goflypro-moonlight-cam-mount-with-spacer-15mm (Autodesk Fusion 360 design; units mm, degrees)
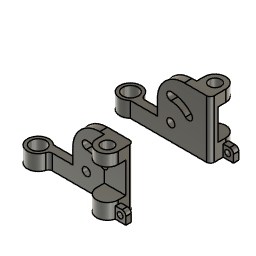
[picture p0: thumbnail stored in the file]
sketch "Skizze1" plane through (0, 0, 0) normal (0, 0, 1) x axis (1, 0, 0)
  line L1 (7.2, 0) -> (-7.2, 0)
  line L2 (7.2, 0) -> (7.2, -2)
  line L3 (-1, 0) -> (-1, 2)
  line L4 (12.8, 2) -> (-8.605, 2)
  line L5 (12.8, 2) -> (12.8, -2)
  line L6 (12.8, 0) -> (7.2, 0)
  line L7 (11, -2) -> (11, 2)
  line L8 (12.8, -2) -> (11, -2)
  circle C1 centre (-10, 0) radius 2
  circle C2 centre (10, -2) radius 1.55
  circle C3 centre (-10, 0) radius 2.8
  circle C4 centre (10, -2) radius 2.8
  point P6 (-7.2, 0)
  point P7 (7.2, -2)
  point P10 (-1, 0)
  point P12 (12.8, -2)
  point P14 (12.8, 0)
  point P15 (11, 2)
  concentric C1 C3
  concentric C2 C4
  coincident C3 P6
  horizontal L1
  coincident C4 P7
  tangent C4 L2
  perpendicular L1 L2
  perpendicular L1 L3
  coincident L1 P10
  coincident C4 P12
  tangent C4 L5
  perpendicular L4 L5
  midpoint L5 P14
  coincident L4 P15
  perpendicular L6 L7
  dimension "d1" diameter C1 = 4
  dimension "d2" diameter C2 = 3.1
  dimension "d3" diameter C3 = 5.6
  dimension "d4" diameter C4 = 5.6
extrude "Extrusion1" new body sketch "Skizze1" profile of C1 C3 L1 L3 L4 along normal blind 4 bodies "GoFlyPro - Moonlight-cam mount with spacer - left"
extrude "Extrusion5" new body sketch "Skizze1" profile of C2 C4 L2 L5 L6 L7 L8 along normal blind 4
extrude "Extrusion8" add sketch "Skizze1" profile of C4 L1 L3 L4 L5 L6 L7 along normal blind 15
sketch "Skizze2" plane through (0, 0, 0) normal (0, 1, 0) x axis (1, 0, 0)
  line L1 (7.2, 0) -> (-1, 0)
  line L2 (7.2, -4) -> (7.2, 0)
  line L3 (7.2, -15) -> (7.2, -4)
  line L4 (-1, -15) -> (7.2, -15)
  line L5 (-1, 0) -> (-1, -15)
  circle C1 centre (2.5, -4.25) radius 1.05
  circle C2 centre (2.5, -4.25) radius 4.95
  circle C3 centre (2.5, -4.25) radius 7.05
  circle C4 centre (2.5, -10.25) radius 1.05
  circle C5 centre (7.0963, -8.1067) radius 1.05
  concentric C1 C2
  concentric C2 C3
  dimension "d8" diameter C1 = 2.1
  dimension "d32" diameter C4 = 2.1
  dimension "d64" diameter C5 = 2.1
extrude "Extrusion2" cut sketch "Skizze2" profile of C1 C2 C3 C4 C5 L3 along normal blind 2
fillet "Abrundung12" radius 1
work_plane "Arbeitsebene" AlongDistance 12
sketch "Skizze3" plane through (0, 0, 15) normal (0, 0, 1) x axis (-1, 0, 0)
  line L1 (-12.8, -2) -> (-12.8, 2)
  line L2 (-7, -2) -> (-12.8, -2)
  line L3 (-7, 0) -> (-7, -2)
  line L4 (-7.2, 0) -> (-7, 0)
  line L5 (-11.9596, 0) -> (-7.2, 0)
  line L6 (1, 0) -> (1, -2)
  line L7 (-7.2, 0) -> (1, 0)
  line L8 (-12.8, 0) -> (-7.2, 0)
  line L9 (-12.8, -2) -> (-12.8, 0)
  line L10 (1, -2) -> (-12.8, -2)
  line L11 (-11.9596, 0) -> (-12.8, 0)
  line L12 (-12.8, 2) -> (-12.8, 0)
  line L13 (-8.0404, 0) -> (-7.2, 0)
  line L14 (-7.2, 2) -> (-7.2, 0)
  circle C1 centre (-10, 2) radius 1.55
  circle C2 centre (-10, 2) radius 2.8
  arc A1 centre (-10, 2) radius 2.8 clockwise from (-11.9596, 0) to (-12.8, 2)
  point P14 (-12.8, 0)
  point P16 (-12.8, 0)
  point P2 (-11.9596, 0)
  point P17 (-11.9596, 0)
  point P18 (-12.8, 0)
  point P3 (-12.8, 2)
  point P19 (-12.8, 2)
  point P13 (-7.2, 0)
  point P20 (-7.2, 0)
  point P21 (-8.0404, 0)
  point P22 (-7.2, 0)
  point P23 (-7.2, 2)
  concentric C1 C2
  coincident P14 P16
  coincident P2 P17
  coincident P14 P18
  coincident P3 P19
  coincident P13 P20
  coincident C2 P21
  coincident L5 P21
  coincident P13 P22
  coincident C2 P23
  tangent C2 L14
  dimension "d77" diameter C1 = 3.1
  dimension "d78" diameter C2 = 5.6
extrude "Extrusion10" add sketch "Skizze3" profile of L1 C1 C2 L5 A1 L8 L11 L12 L13 L14 against normal blind 3
extrude "Extrusion11" cut sketch "Skizze1" profile of C2 L7 L8 along normal blind 3.2
extrude "Extrusion12" cut sketch "Skizze3" profile of C1 against normal blind 3
combine "Kombinieren"
fillet "Abrundung20" radius 7
fillet "Abrundung21" radius 1
sketch "Skizze4" plane through (0, 0, 0) normal (0, 0, 1) x axis (1, 0, 0)
  line L1 (12.5, -2.7) -> (15.5, -2.7)
  line L2 (12.5, -1.3) -> (12.5, -2.7)
  line L3 (15.5, -1.3) -> (12.5, -1.3)
  line L4 (15.5, -2.7) -> (15.5, -1.3)
  horizontal L1
  vertical L2
  horizontal L3
  vertical L4
extrude "Extrusion13" add sketch "Skizze4" along normal blind 3
sketch "Skizze5" plane through (0, -2.7, 0) normal (0, -1, 0) x axis (1, 0, 0)
  line L1 (12.7111, 0) -> (12.7111, 3)
  line L2 (15.5, 0) -> (12.7111, 0)
  line L3 (15.5, 3) -> (15.5, 0)
  line L4 (12.7111, 3) -> (15.5, 3)
  circle C1 centre (14, 1.5) radius 0.75
  dimension "d93" diameter C1 = 1.5
extrude "Extrusion14" cut sketch "Skizze5" profile of C1 against normal blind 1.4
fillet "Abrundung22" radius 1
mirror "Spiegeln" mirrorStitchTolerance 0.1 bodies "GoFlyPro - Moonlight-cam mount with spacer - right"
named bodies: "GoFlyPro - Moonlight-cam mount with spacer - left", "GoFlyPro - Moonlight-cam mount with spacer - right"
